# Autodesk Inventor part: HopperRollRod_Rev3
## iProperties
Created: 2009-01
Part Number: HopperRollRod_Rev3
Document SubType Name: Modeling
Designer: claivier
Material: Acier
Norme de conversion: STEP AP214IS
Nom du fichier: HopperRollRod_Rev3.STEP
Préprocesseur: SolidWorks 2008
Postprocesseur: Build: 344a, Release: 11 SP2 - Date: Fri 08/18/2006
Unités envoyées: INCHES
Incertitude: 1e-05
Author: claivier
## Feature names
1. Base1
